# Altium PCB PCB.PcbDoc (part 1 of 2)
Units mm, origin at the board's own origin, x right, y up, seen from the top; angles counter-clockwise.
Board outline 68.58 x 53.34 mm, 4 copper layers (TOP, GND, SIG, BOTTOM), stack 1.586 mm thick; 137 components, 78 nets, 396 pads, 160 vias.
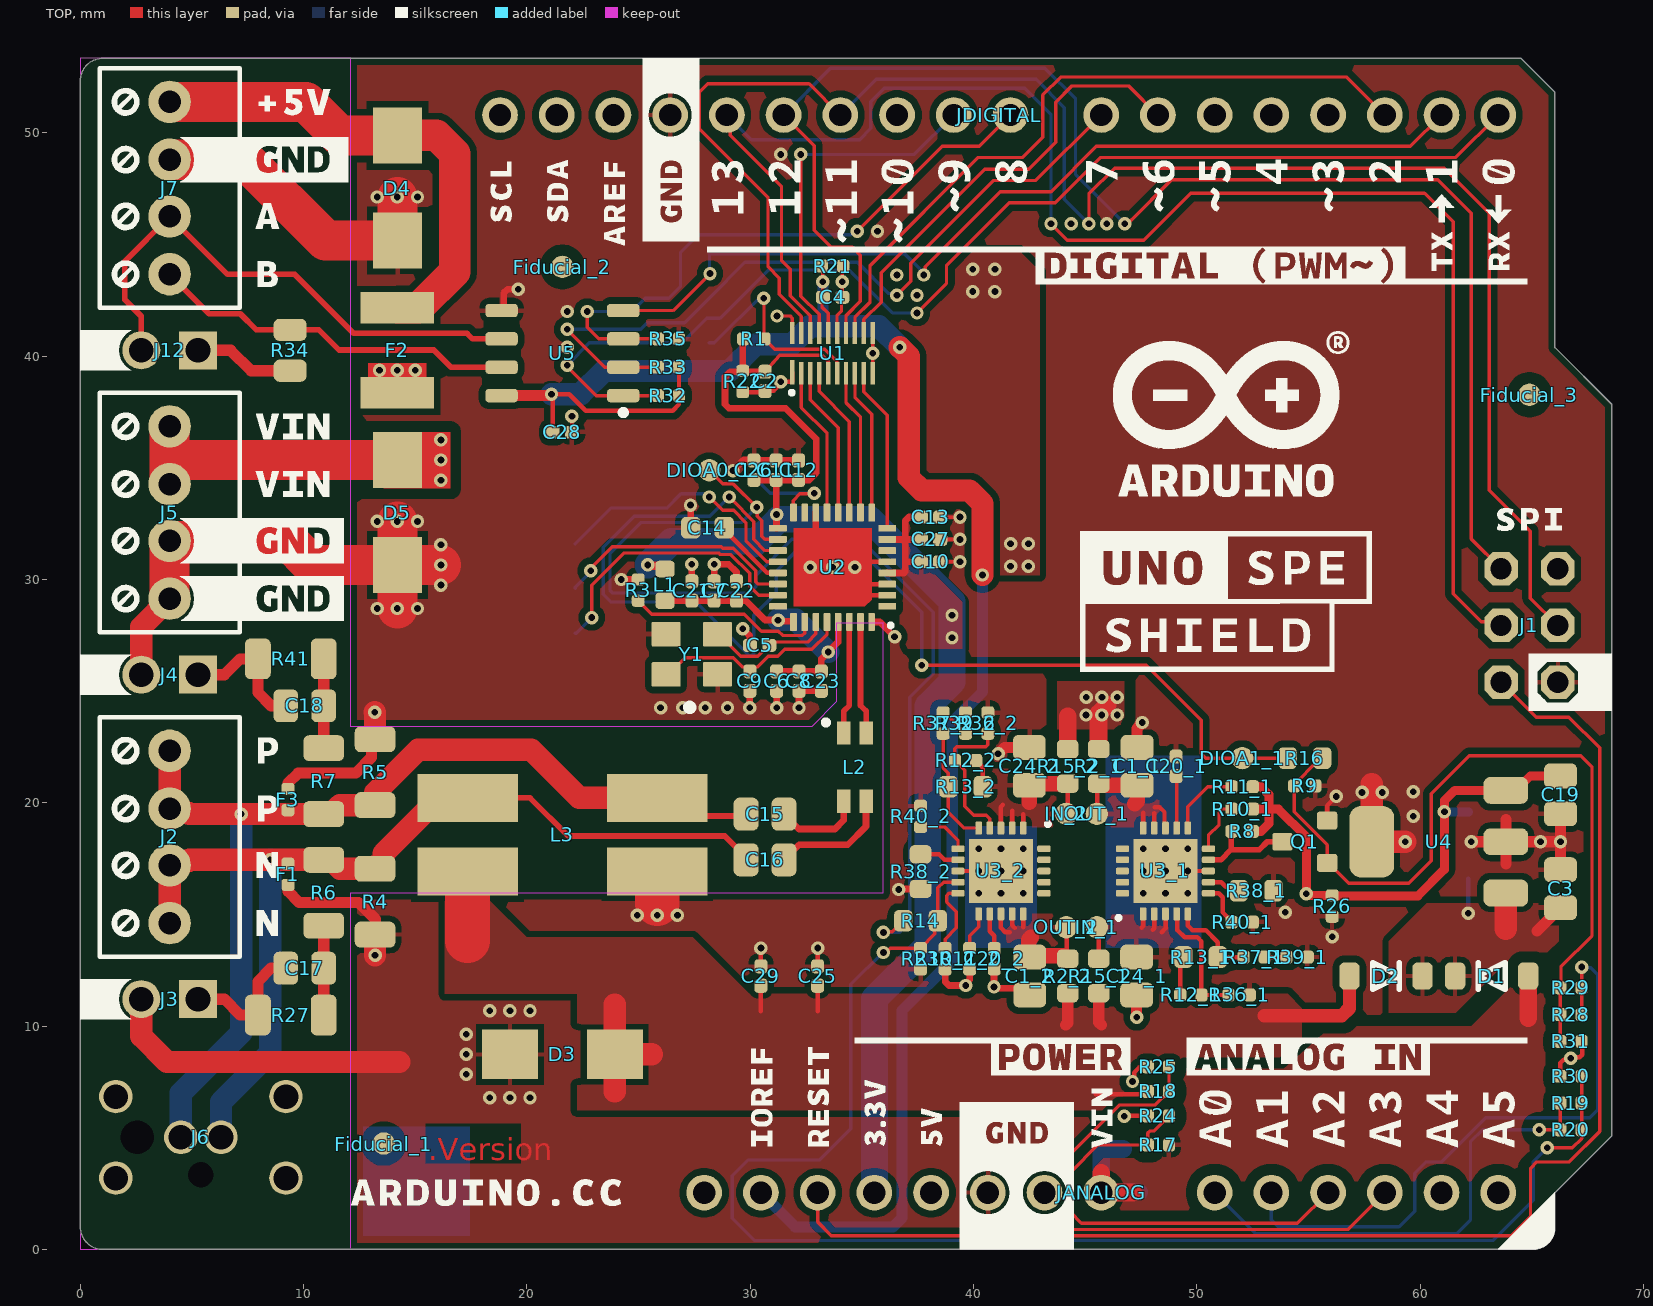
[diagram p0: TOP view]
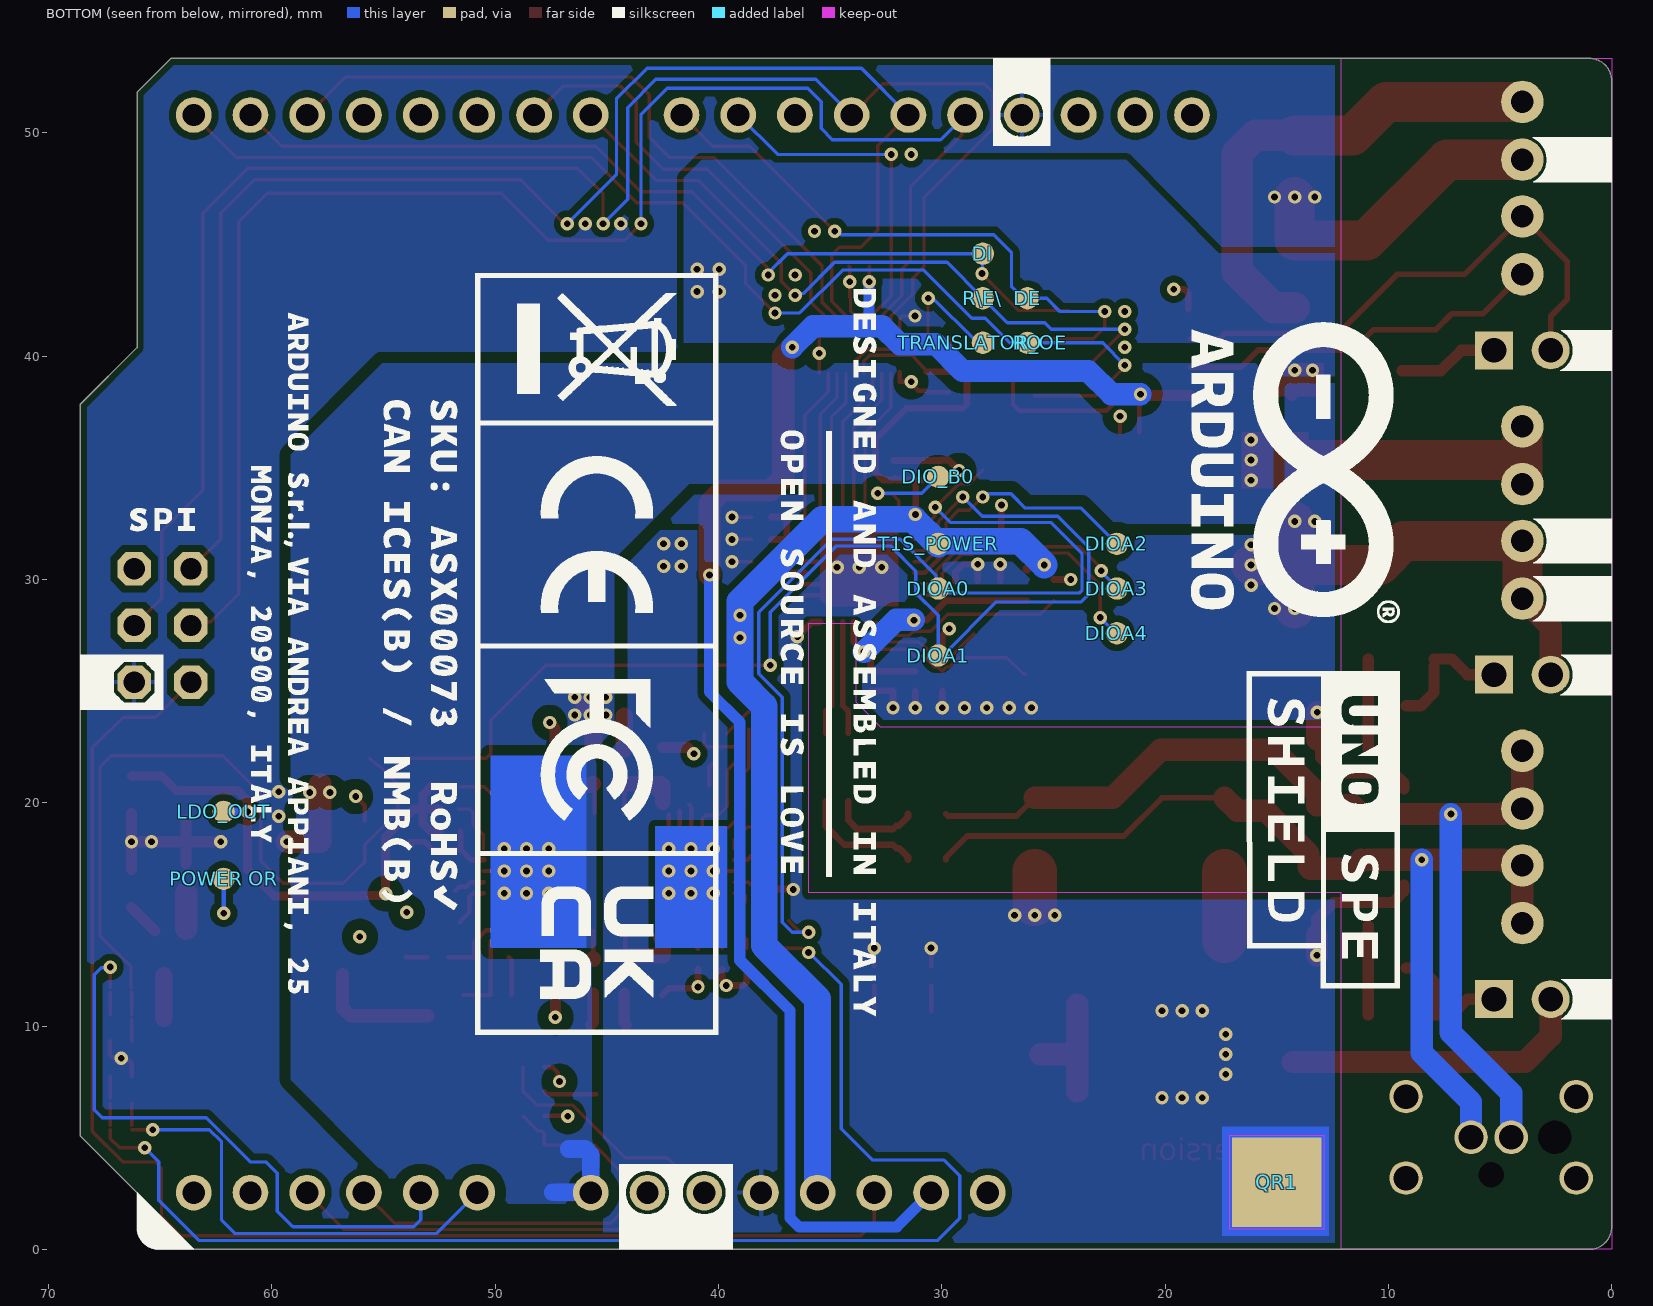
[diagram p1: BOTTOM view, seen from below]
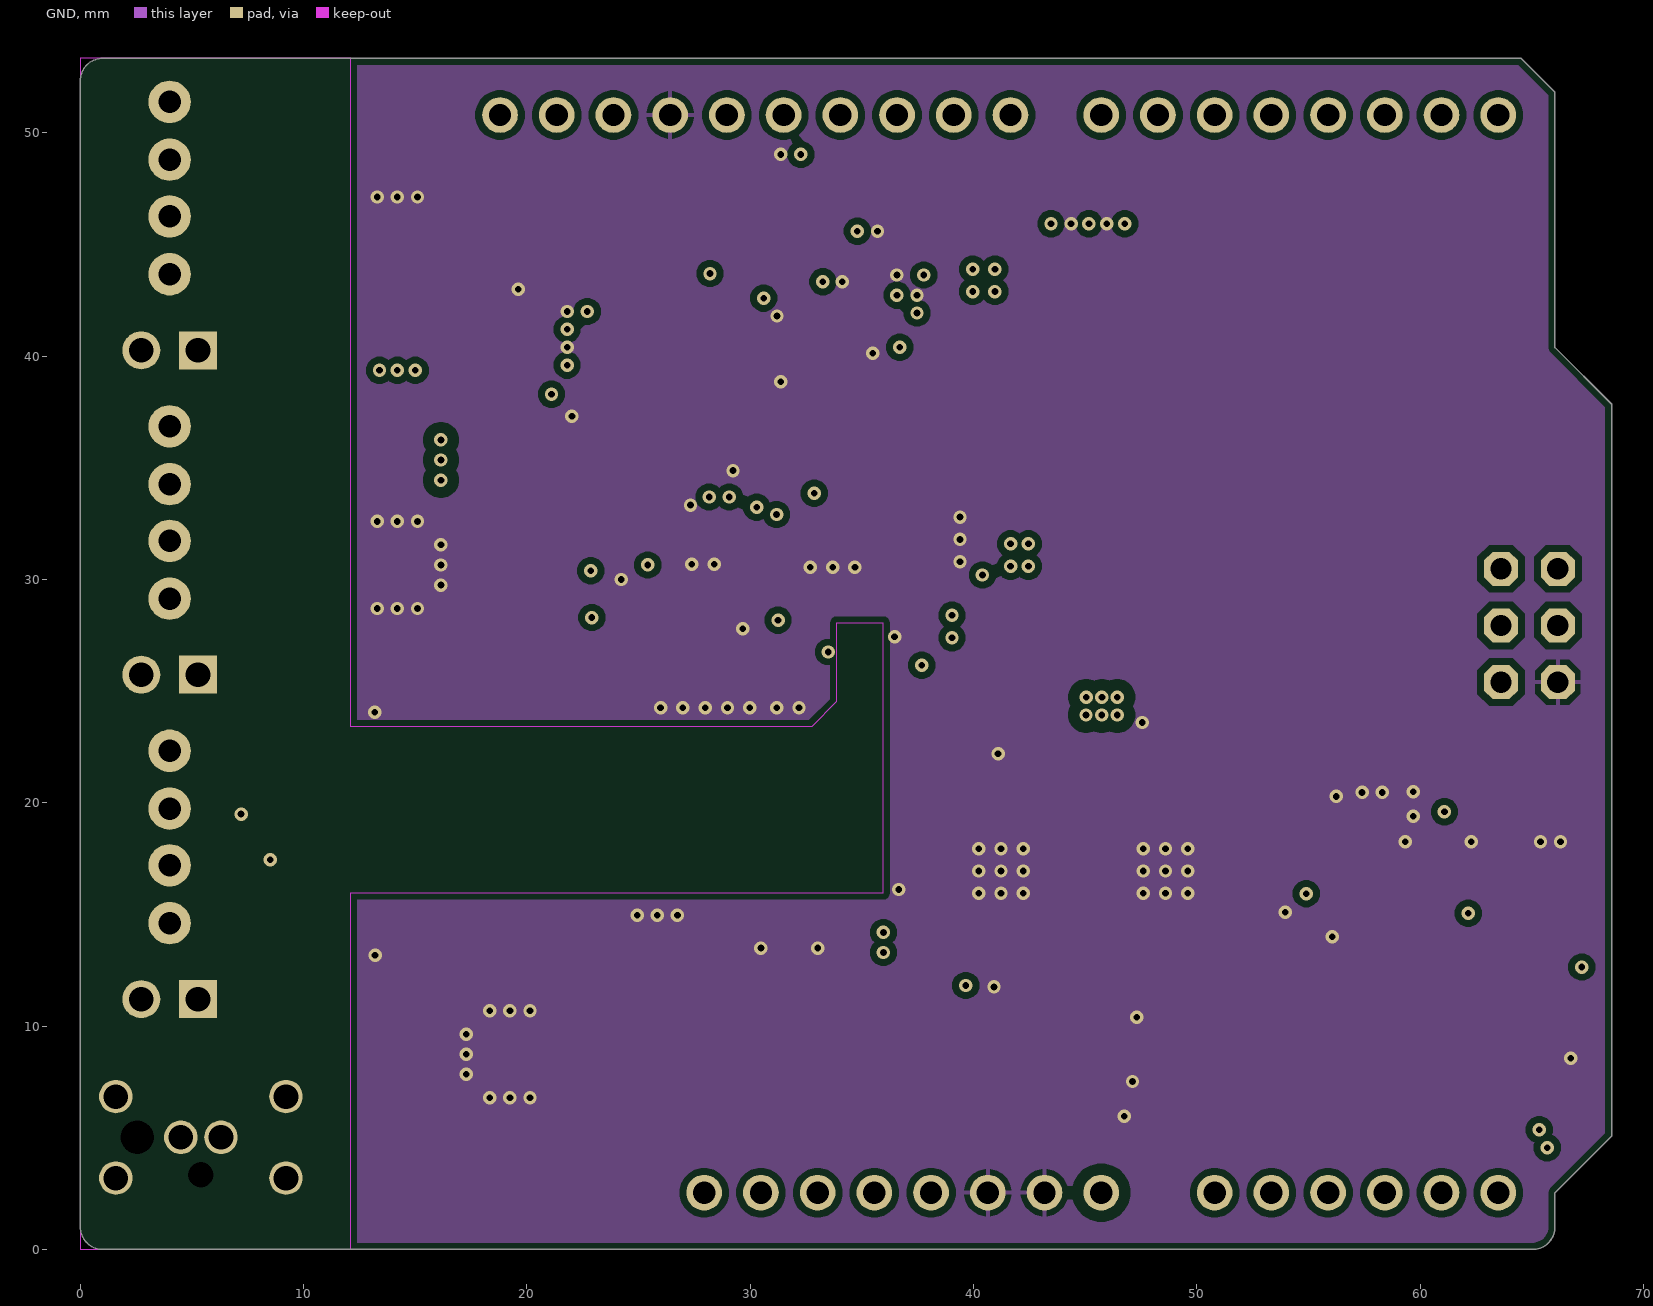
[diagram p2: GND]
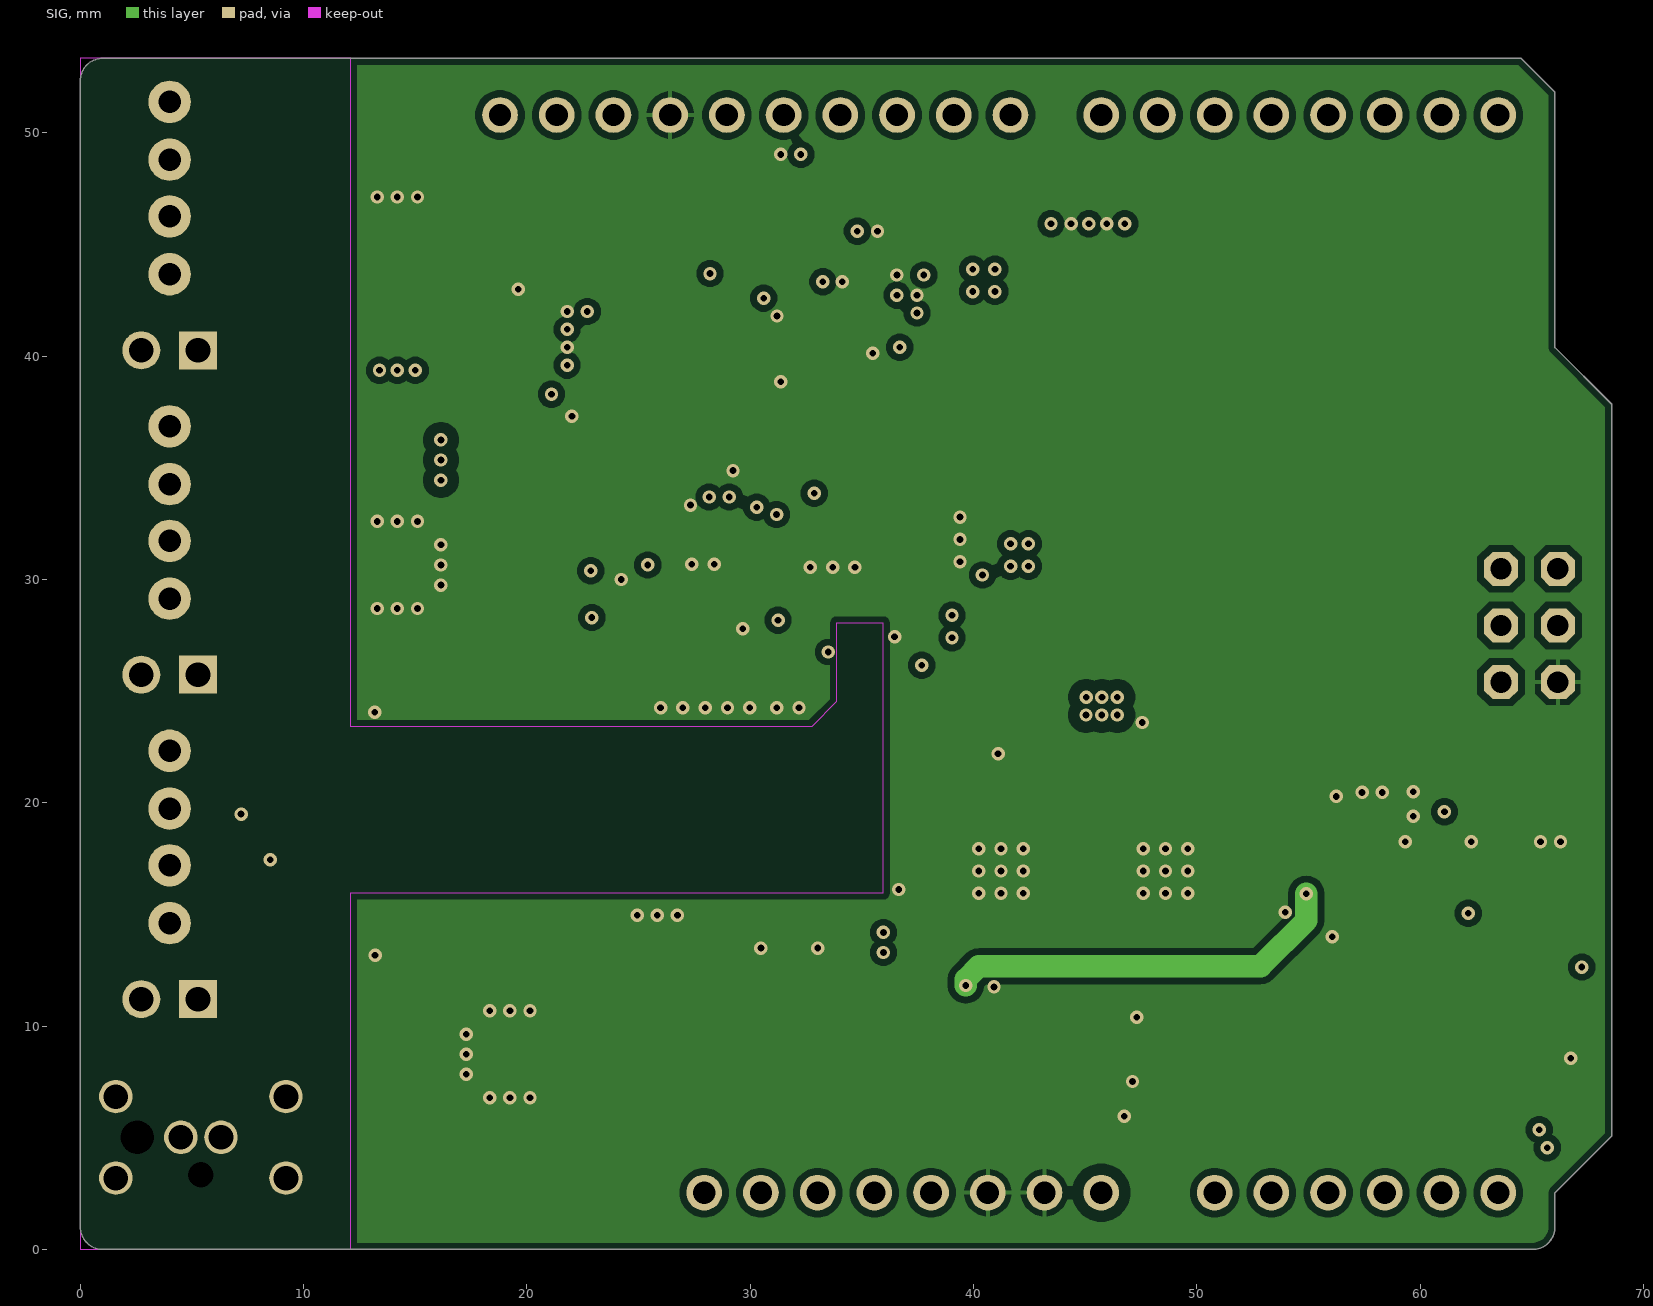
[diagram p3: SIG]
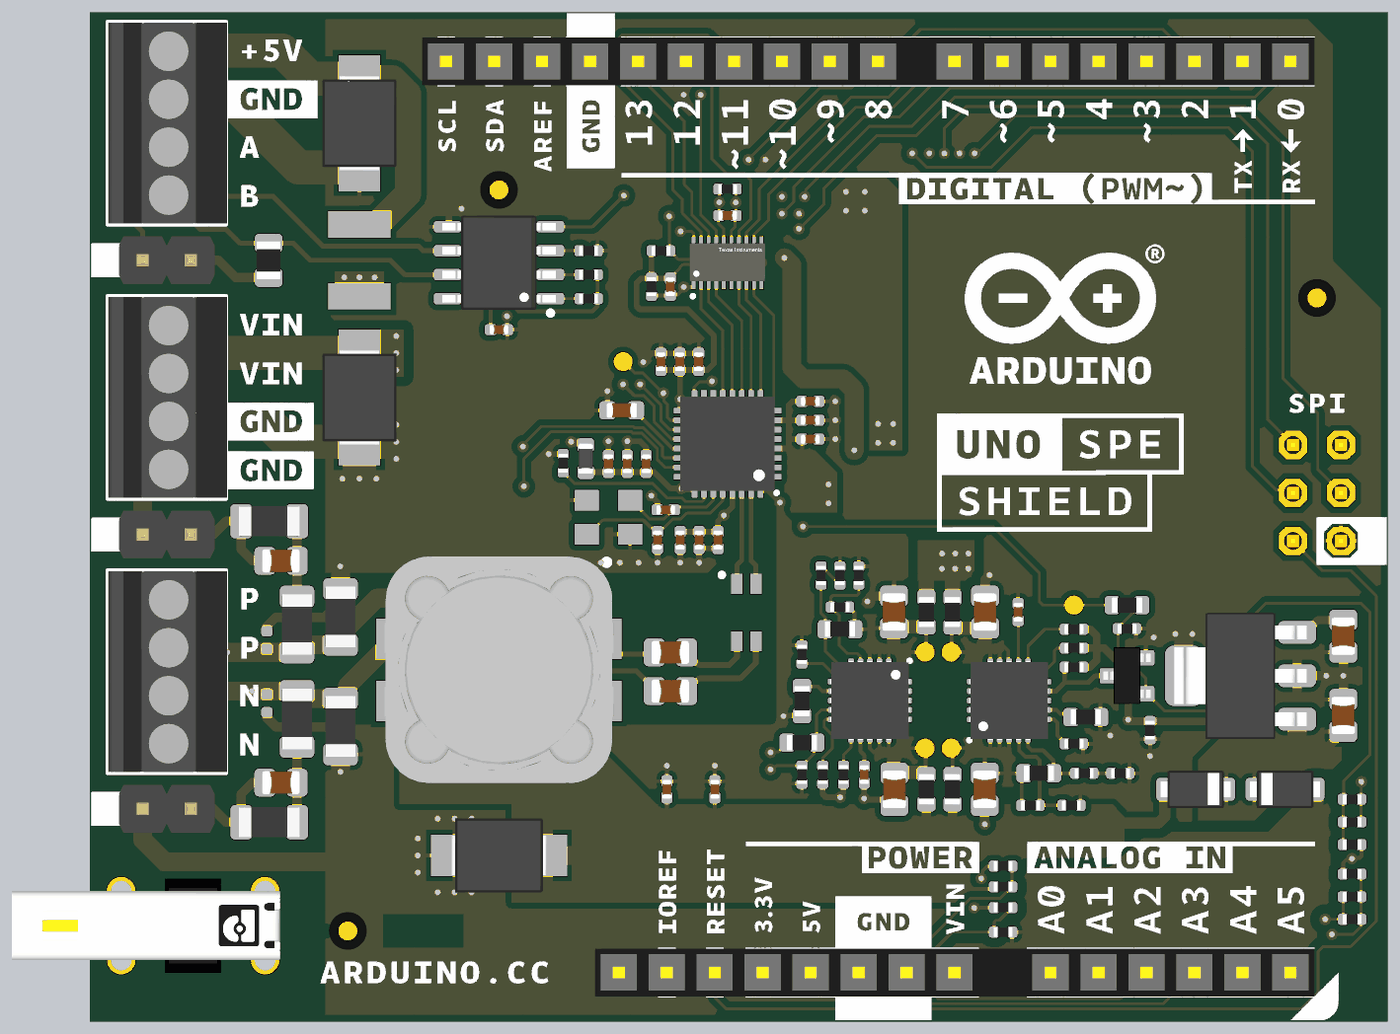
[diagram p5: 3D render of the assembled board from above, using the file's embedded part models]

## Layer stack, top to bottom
Top Solder: solder mask 0.0102, Solder Resist, Dk 3.5
TOP: signal copper 0.018
Dielectric 1: prepreg 0.14, PP-014, Dk 4.2
GND: signal copper 0.035
Dielectric2: core 1.2, FR-4, Dk 4.8
SIG: signal copper 0.035
Dielectric3: prepreg 0.14, PP-014, Dk 4.2
BOTTOM: signal copper 0.018
Bottom Solder: solder mask 0.0102, Solder Resist, Dk 3.5

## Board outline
0,1 0,52.34 cw(c1,52.34) 1,53.34 64.516,53.34 66.04,51.816 66.04,40.386 68.58,37.846 68.58,5.08 66.04,2.54 66.04,1 cw(c65.04,1) 65.04,0 1,0 cw(c1,1)

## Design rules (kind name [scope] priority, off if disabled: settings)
BoardOutlineClearance Silks [(OnLayer('Top Overlay') OR OnLayer('Bottom Overlay'))] p1: gap=0 ignorepadtopadclearanceinfootprint=FALSE
BoardOutlineClearance [All] p2: gap=0.3 ignorepadtopadclearanceinfootprint=FALSE
Clearance VIN_0.5mm [InNet('VIN')] p1: gap=0.5 ignorepadtopadclearanceinfootprint=TRUE
Clearance QR [InComponent('QR1') vs InNet('GND')] p2: gap=0 ignorepadtopadclearanceinfootprint=FALSE
Clearance COPPER_0.3mm [All] p3: gap=0.127 ignorepadtopadclearanceinfootprint=FALSE except(0.3: Arc-Fill Arc-Poly Arc-Region Track-Fill Track-Poly Track-Region SMDPad-Fill SMDPad-Poly SMDPad-Region THPad-Fill THPad-Poly THPad-Region Via-Fill Via-Poly Via-Region Fill-Fill Fill-Poly Fill-Region Poly-Poly Poly-Region Region-Region)
Clearance "Generic clearance 0.127mm" [All] p4: gap=0.127 ignorepadtopadclearanceinfootprint=FALSE
ComponentClearance [All] p1: gap=0.2 collisioncheckmode=3 verticalgap=0 showdistances=TRUE
DiffPairsRouting USB [InDifferentialPairClass('USB')] p1: maxlimit=0.254 minlimit=0.15 mostfreqgap=0.254 toplayer_maxgap=0.15 toplayer_prefgap=0.15 toplayer_minwidth=0.15 toplayer_maxwidth=0.21 toplayer_prefwidth=0.2 midlayer2_mingap=0.24 midlayer2_maxgap=0.24 midlayer2_prefgap=0.24 midlayer2_minwidth=0.15 midlayer2_maxwidth=0.15 midlayer2_prefwidth=0.15 bottomlayer_maxgap=0.15 bottomlayer_prefgap=0.15 bottomlayer_minwidth=0.15 bottomlayer_maxwidth=0.21 bottomlayer_prefwidth=0.2 impedanceprofiledriven=TRUE impedanceprofileid={E6B00C31-4C8E-439C-824F-D2B2CDC26F9C} impedanceprofilevalue=90.000000 maxuncoupledlength=12.7
Height [All] p1: minheight=0 maxheight=30 prefheight=12.7
HoleSize [All] p1: absolutevalues=TRUE maxlimit=30 minlimit=0.3 maxpercent=80.000 minpercent=20.000
HoleToHoleClearance [All] p1: gap=0.25 allowstackedmicrovias=FALSE
MinimumAnnularRing [All] p1: minimumring=0.15
PlaneConnect [All] p1: pad.planeconnectstyle=Relief pad.reliefexpansion=0.508 pad.reliefentries=4 pad.reliefconductorwidth=0.254 pad.reliefairgap=0.254 via.planeconnectstyle=Direct via.reliefexpansion=0.508 via.reliefentries=4 via.reliefconductorwidth=0.254 via.reliefairgap=0.254
PolygonConnect [All] p1: thpad.connectstyle=Relief thpad.reliefconductorwidth=0.2 thpad.reliefentries=4 thpad.polygonreliefangle="90 Angle" thpad.airgapwidth=0.254 smdpad.connectstyle=Relief smdpad.reliefconductorwidth=0.2 smdpad.reliefentries=4 smdpad.polygonreliefangle="90 Angle" smdpad.airgapwidth=0.254 via.connectstyle=Direct via.reliefconductorwidth=0.254 via.reliefentries=4 via.polygonreliefangle="90 Angle" via.airgapwidth=0.254
RoomDefinition U_SWITCH2 [InComponentClass('U_SWITCH2')] p1: confinementstyle=ConfineIn formatcopy=TRUE lockcomponents=FALSE outline 18.045,37.041 18.045,39.371 20.715,39.371 20.715,41.631 22.715,41.631 26.045,41.631 26.045,39.371 28.715,39.371 28.715,37.041 28.44,37.041 28.44,35.646 25.383,35.646 25.383,34.926 21.005,34.926 21.005,34.641 18.755,34.641 18.755,35.646 18.32,35.646 18.32,37.041
RoomDefinition U_SWITCH1 [InComponentClass('U_SWITCH1')] p2: confinementstyle=ConfineIn formatcopy=TRUE lockcomponents=FALSE outline 18.045,30.041 18.045,32.371 20.715,32.371 20.715,34.631 22.715,34.631 26.045,34.631 26.045,32.371 28.715,32.371 28.715,30.041 28.44,30.041 28.44,28.646 25.383,28.646 25.383,27.926 21.005,27.926 21.005,27.641 18.755,27.641 18.755,28.646 18.32,28.646 18.32,30.041
RoomDefinition TOP [InComponentClass('TOP')] p3: confinementstyle=ConfineIn formatcopy=TRUE lockcomponents=FALSE outline 73.6,19.987 86.9,19.987 86.9,30.187 73.6,30.187
RoutingVias StandardVias [All] p1: holewidth=0.3 width=0.6 viastyle="Through Hole" minholewidth=0.3 minwidth=0.6 maxholewidth=0.3 maxwidth=0.6
SMDToCorner [All] p1: distance=39370
SilkToSilkClearance [All] p1: silktosilkclearance=0.2
SilkToSolderMaskClearance [IsPad] p1: minsilkscreentomaskgap=0.15 clearancetoexposedcopper=TRUE
SolderMaskExpansion VIAtented [IsVia] p1: expansion=0.102 istentingtop=TRUE
SolderMaskExpansion [All] p2: expansion=0.05 istentingtop=FALSE
SupplyNets "Schematic Supply Nets_6" [InNet('GND')] p1: voltage=0.000
SupplyNets "Schematic Supply Nets_5" [InNet('LDO_OUT')] p2: voltage=0.000
SupplyNets "Schematic Supply Nets_4" [InNet('IOREF')] p3: voltage=0.000
SupplyNets "Schematic Supply Nets_3" [InNet('VIN')] p4: voltage=0.000
SupplyNets "Schematic Supply Nets_2" [InNet('T1S_POWER')] p5: voltage=0.000
SupplyNets "Schematic Supply Nets_1" [InNet('+3V3')] p6: voltage=0.000
SupplyNets "Schematic Supply Nets" [InNet('+5V')] p7: voltage=0.000
UnConnectedPin [All] p1:
UnRoutedNet [All] p1: checkbadconnections=TRUE
ViasUnderSMD [All] p1: allowed=FALSE
Width StandardTraces [All] p1: maxlimit=5 minlimit=0.127 preferedwidth=0.15
21 further rules are at their usual default settings.

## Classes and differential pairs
component class "U_UART-RS485 Transceiver": C28 DE DI J12 R32 R33 R34 R35 R\E\ RO U5
component class U_T1S_POWER: C3 C19 D1 D2 LDO_OUT "POWER OR" Q1 R8 R9 R23 R26 U4
component class U_SWITCH1: C1_1 C20_1 C24_1 IN_1 OUT_1 R2_1 R10_1 R11_1 R12_1 R13_1 R15_1 R36_1 R37_1 R38_1 R39_1 R40_1 U3_1
channel class SWITCH: U_SWITCH1 U_SWITCH2
component class U_SWITCH2: C1_2 C20_2 C24_2 IN_2 OUT_2 R2_2 R10_2 R11_2 R12_2 R13_2 R15_2 R36_2 R37_2 R38_2 R39_2 R40_2 U3_2
component class U_T1S: C2 C4 C5 C6 C7 C8 C9 C10 C11 C12 C13 C14 C21 C22 C23 C26 C27 L1 R1 R3 R21 R22 T1S_POWER TRANSLATOR_OE U1 U2 Y1
component class TOP: + C15 C16 C17 C18 C25 C29 D3 D4 D5 DIO_B0 DIOA0 DIOA0_1 DIOA1 DIOA1_1 DIOA2 DIOA3 DIOA4 F1 F2 F3 Fiducial_1 Fiducial_2 Fiducial_3 J1 J2 J3 J4 J5 J6 J7 JANALOG JDIGITAL L2 L3 QR1 R4 R5 R6 R7 R14 R16 R17 R18 R19 R20 R24 R25 R27 R28 R29 R30 R31 R41

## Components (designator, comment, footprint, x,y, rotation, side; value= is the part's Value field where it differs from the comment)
C1_1 "GRM21BR61H106ME43L" CAP-0805 47.326,21.632 r90 top value=10µF (schematic designator C1)
C1_2 "GRM21BR61H106ME43L" CAP-0805 42.52,12.242 r270 top value=10µF (schematic designator C1)
C2 "GRM155R61H104KE19D" CAP-0402 30.665,38.87 r90 top value=100nF
C3 "GRM21BR61H106ME43L" CAP-0805 66.29,16.156 r90 top value=10µF
C4 "GRM155R61H104KE19D" CAP-0402 33.69,42.638 r180 top value=100nF
C5 "C0402H100J5GACTU" CAP-0402 30.42,27.05 r0 top value=10pF
C6 "GRM155R60J106ME05D" CAP-0402 31.185,25.45 r90 top value=10µF
C7 "GRM155R61H104KE19D" CAP-0402 28.385,29.485 r270 top value=100nF
C8 "C1005B103K500NT" CAP-0402 32.185,25.45 r90 top value=10nF
C9 "C0402H100J5GACTU" CAP-0402 29.985,25.45 r90 top value=10pF
C10 "GRM155R60J106ME05D" CAP-0402 38.075,30.795 r180 top value=10µF
C11 "C1005B103K500NT" CAP-0402 31.165,34.895 r270 top value=10nF
C12 "GRM155R61H104KE19D" CAP-0402 32.165,34.895 r270 top value=100nF
C13 "GRM155R61H104KE19D" CAP-0402 38.075,32.795 r180 top value=100nF
C14 "GRM188R61C475KAAJD" CAP-0603 28.085,32.32 r0 top value=4.7µF
C15 "08055C104K4T2A" CAP-0805 30.665,19.495 r180 top value=100nF
C16 "08055C104K4T2A" CAP-0805 30.665,17.445 r180 top value=100nF
C17 "CL21B224KBFNNNF" CAP-0805 10.05,12.595 r180 top value=220nF
C18 "CL21B224KBFNNNF" CAP-0805 10.05,24.345 r180 top value=220nF
C19 "GRM21BR61H106ME43L" CAP-0805 66.29,20.356 r270 top value=10µF
C20_1 "GRM155R61H104KE19D" CAP-0402 49.077,21.632 r270 top value=100nF (schematic designator C20)
C20_2 "GRM155R61H104KE19D" CAP-0402 40.929,13.017 r90 top value=100nF (schematic designator C20)
C21 "GRM155R60J106ME05D" CAP-0402 27.385,29.485 r270 top value=10µF
C22 "C1005B103K500NT" CAP-0402 29.385,29.485 r270 top value=10nF
C23 "GRM155R61H104KE19D" CAP-0402 33.185,25.45 r90 top value=100nF
C24_1 "GRM21BR61H106ME43L" CAP-0805 47.305,12.242 r270 top value=10µF (schematic designator C24)
C24_2 "GRM21BR61H106ME43L" CAP-0805 42.499,21.632 r90 top value=10µF (schematic designator C24)
C25 "GRM155R61H104KE19D" CAP-0402 33.02,12.242 r270 top value=100nF
C26 "GRM155R60J106ME05D" CAP-0402 30.165,34.895 r270 top value=10µF
C27 "C1005B103K500NT" CAP-0402 38.075,31.795 r180 top value=10nF
C28 "GRM155R61H104KE19D" CAP-0402 21.59,36.595 r180 top value=100nF
C29 "C1005B103K500NT" CAP-0402 30.48,12.242 r270 top value=10nF
D1 "PMEG6020AELRX" SOD123-1 63.207,12.242 r0 top
D2 "PMEG6020AELRX" SOD123-1 58.473,12.242 r180 top
D3 "SMBJ24CA" SMB_NOPOLARITY 21.59,8.737 r180 top
D4 "SMBJ5.0CA" SMB_NOPOLARITY 14.2,47.53 r90 top
D5 "SMBJ24CA" SMB_NOPOLARITY 14.2,33 r270 top
DE "Test point 1.00mm" TP-1.00MM 26.16,42.595 r180 bottom
DI "Test point 1.00mm" TP-1.00MM 28.16,44.595 r180 bottom
DIO_B0 "Test point 1.00mm" TP-1.00MM 30.16,34.595 r270 bottom
DIOA0 "Test point 1.00mm" TP-1.00MM 30.16,29.595 r270 bottom
DIOA0_1 "Test point 1.00mm" TP-1.00MM 28.165,34.895 r90 top
DIOA1 "Test point 1.00mm" TP-1.00MM 30.16,26.595 r180 bottom
DIOA1_1 "Test point 1.00mm" TP-1.00MM 52.033,22 r90 top
DIOA2 "Test point 1.00mm" TP-1.00MM 22.16,31.595 r270 bottom
DIOA3 "Test point 1.00mm" TP-1.00MM 22.16,29.595 r270 bottom
DIOA4 "Test point 1.00mm" TP-1.00MM 22.16,27.595 r270 bottom
F1 "AVRH10C221KT1R5YA8" "PASSIVE 0402" 9.3,16.795 r90 top
F2 "MF-MSMF050-2-W2" 1812 14.2,40.265 r90 top
F3 "AVRH10C221KT1R5YA8" "PASSIVE 0402" 9.3,20.145 r270 top
Fiducial_1 "Fiducial mark 1mm with 2mm solder" "Fiducial mark 1mm with circle-Footprint-1" 13.59,4.74 r90 top
Fiducial_2 "Fiducial mark 1mm with 2mm solder" "Fiducial mark 1mm with circle-Footprint-1" 21.59,44 r90 top
Fiducial_3 "Fiducial mark 1mm with 2mm solder" "Fiducial mark 1mm with circle-Footprint-1" 64.897,38.273 r90 top
IN_1 "Test point 1.00mm" TP-1.00MM 45.526,14.425 r0 top (schematic designator IN)
IN_2 "Test point 1.00mm" TP-1.00MM 44.156,19.505 r90 top (schematic designator IN)
J1 "RSE2-1-06-SG-3" RSE2-1-06-SG-3 64.897,27.94 r90 top
J2 "DG308-2.54-04P-13-00Z(H)" DG308-2.54-04P 4,18.47 r90 top
J3 "61300211121" 61300211121 4,11.205 r180 top
J4 "61300211121" 61300211121 4,25.735 r180 top
J5 "DG308-2.54-04P-13-00Z(H)" DG308-2.54-04P 4,33 r90 top
J6 "1163797" 1163797 5.4,5.02 r0 top
J7 "DG308-2.54-04P-13-00Z(H)" DG308-2.54-04P 4,47.53 r90 top
J12 "61300211121" 61300211121 4,40.265 r180 top
JANALOG "20TW-988" 20TW-988 45.72,2.54 r0 top locked
JDIGITAL "20TW-987" 20TW-987 45.72,50.8 r180 top locked
L1 "BLM18KG331SN1D" L-0603 26.185,29.76 r270 top
L2 "DLW32MH201XK2L" DLW32MH 34.69,21.6 r270 top
L3 "SRF1260A-221M" SRF1260 21.59,18.57 r180 top
LDO_OUT "Test point 1.00mm" TP-1.00MM 62.16,19.595 r90 bottom
OUT_1 "Test point 1.00mm" TP-1.00MM 45.526,19.505 r0 top (schematic designator OUT)
OUT_2 "Test point 1.00mm" TP-1.00MM 44.156,14.425 r90 top (schematic designator OUT)
"POWER OR" "Test point 1.00mm" TP-1.00MM 62.16,16.595 r90 bottom
Q1 "2N7002KT1G" SOT23 54.84,18.256 r90 top
QR1 "QR CODE 4x4mm" "QR CODE 4x4mm" 15,3 r180 bottom
R1 "CRCW0402100KFKEDC" RES-0402 30.165,40.775 r0 top value=100k
R2_1 "CRCW06030000Z0EAC" RES-0603 45.605,21.632 r270 top value=0 (schematic designator R2)
R2_2 "CRCW06030000Z0EAC" RES-0603 44.22,12.242 r90 top value=0 (schematic designator R2)
R3 "CRCW040212K4FKED" RES-0402 24.985,29.525 r90 top value=12.4k
R4 "RC1206FR-0710KL" RES-1206 13.2,15.57 r270 top value=10k
R5 "RC1206FR-0710KL" RES-1206 13.2,21.37 r90 top value=10k
R6 "RC1206FR-0749R9L" RES-1206 10.9,15.97 r270 top value=49.9
R7 "RC1206FR-0749R9L" RES-1206 10.9,20.97 r90 top value=49.9
R8 "CRCW040210K0FKED" RES-0402 52.033,18.72 r180 top value=10k
R9 "CRCW0402100KFKEDC" RES-0402 54.84,20.756 r0 top value=100k
R10_1 "CRCW040210K0FKED" RES-0402 52.033,19.72 r0 top value=10k (schematic designator R10)
R10_2 "CRCW040210K0FKED" RES-0402 38.729,13.017 r270 top value=10k (schematic designator R10)
R11_1 "CRCW040210K0FKED" RES-0402 52.033,20.72 r0 top value=10k (schematic designator R11)
R11_2 "CRCW040210K0FKED" RES-0402 39.829,13.017 r270 top value=10k (schematic designator R11)
R12_1 "RC0402FR-072M4L" RES-0402 49.733,11.392 r180 top value=2.4M (schematic designator R12)
R12_2 "RC0402FR-072M4L" RES-0402 39.642,21.897 r0 top value=2.4M (schematic designator R12)
R13_1 "RC0603FR-07470KL" RES-0603 50.168,13.092 r180 top value=470k (schematic designator R13)
R13_2 "RC0603FR-07470KL" RES-0603 39.642,20.72 r0 top value=470k (schematic designator R13)
R14 "CRCW06030000Z0EAC" RES-0603 37.629,14.717 r0 top value=0
R15_1 "CRCW06030000Z0EAC" RES-0603 45.605,12.242 r270 top value=0 (schematic designator R15)
R15_2 "CRCW06030000Z0EAC" RES-0603 44.22,21.632 r90 top value=0 (schematic designator R15)
R16 "CRCW06030000Z0EAC" RES-0603 54.842,22 r180 top value=0
R17 "CRCW040210K0FKED" RES-0402 48.28,4.675 r0 top value=10k
R18 "CRCW040210K0FKED" RES-0402 48.28,7.075 r180 top value=10k
R19 "CRCW040210K0FKED" RES-0402 66.757,6.554 r180 top value=10k
R20 "CRCW040210K0FKED" RES-0402 66.757,5.354 r180 top value=10k
R21 "CRCW0402100KFKEDC" RES-0402 33.69,44.038 r0 top value=100k
R22 "CRCW0402100KFKEDC" RES-0402 29.665,38.87 r270 top value=100k
R23 "CRCW04021K50JNED" RES-0402 37.629,13.017 r270 top value=1.5k
R24 "CRCW04021K50JNED" RES-0402 48.28,5.975 r0 top value=1.5k
R25 "CRCW04021K50JNED" RES-0402 48.28,8.175 r0 top value=1.5k
R26 "CRCW0402100KFKEDC" RES-0402 56.064,15.374 r270 top value=100k
R27 "RV1206FR-07100KL" RES-1206 9.425,10.495 r180 top value=100k
R28 "CRCW040210K0FKED" RES-0402 66.757,10.513 r0 top value=10k
R29 "CRCW040210K0FKED" RES-0402 66.757,11.713 r0 top value=10k
R30 "CRCW040210K0FKED" RES-0402 66.757,7.754 r0 top value=10k
R31 "CRCW040210K0FKED" RES-0402 66.757,9.313 r180 top value=10k
R32 "CRCW040210K0FKED" RES-0402 26.336,38.235 r0 top value=10k
R33 "CRCW040210K0FKED" RES-0402 26.336,39.505 r0 top value=10k
R34 "RMCF0805FT120R" RES-0805 9.395,40.265 r90 top value=120
R35 "CRCW040210K0FKED" RES-0402 26.336,40.775 r180 top value=10k
R36_1 "CRCW0402910KFKED" RES-0402 51.894,11.392 r180 top value=910k (schematic designator R36)
R36_2 "CRCW0402910KFKED" RES-0402 40.642,23.572 r270 top value=910k (schematic designator R36)
R37_1 "CRCW040212K4FKED" RES-0402 52.568,13.092 r180 top value=12.4k (schematic designator R37)
R37_2 "CRCW040212K4FKED" RES-0402 38.642,23.572 r270 top value=12.4k (schematic designator R37)
R38_1 "CRCW06032K20FKEAC" RES-0603 52.659,16.066 r180 top value=2.2k (schematic designator R38)
R38_2 "CRCW06032K20FKEAC" RES-0603 37.629,16.917 r90 top value=2.2k (schematic designator R38)
R39_1 "CRCW040212K4FKED" RES-0402 54.491,13.092 r180 top value=12.4k (schematic designator R39)
R39_2 "CRCW040212K4FKED" RES-0402 39.642,23.572 r270 top value=12.4k (schematic designator R39)
R40_1 "RC0402JR-10150KL" RES-0402 52.032,14.653 r180 top value=150k (schematic designator R40)
R40_2 "RC0402JR-10150KL" RES-0402 37.629,19.39 r270 top value=150k (schematic designator R40)
R41 "RV1206FR-07100KL" RES-1206 9.425,26.445 r180 top value=100k
R\E\ "Test point 1.00mm" TP-1.00MM 28.16,42.595 r90 bottom
RO "Test point 1.00mm" TP-1.00MM 26.16,40.595 r180 bottom
T1S_POWER "Test point 1.00mm" TP-1.00MM 30.16,31.595 r180 bottom
TRANSLATOR_OE "Test point 1.00mm" TP-1.00MM 28.16,40.605 r270 bottom
U1 "TXB0108DQSR" FP-DQS0020A-MFG 33.69,40.138 r90 top
U2 "LAN8651B1-E/LMX" PQFN50P500X500X100_HS-33N 33.69,30.545 r180 top
U3_1 "MAX17613AATP+T" QFN50P400X400X80_HS-21N 48.596,16.945 r90 top (schematic designator U3)
U3_2 "MAX17613AATP+T" QFN50P400X400X80_HS-21N 41.229,16.945 r270 top (schematic designator U3)
U4 "MCP1799T-5002H/DB" SOT223-3 60.84,18.256 r180 top
U5 "XR33058IDTR-F" SOIC8 21.59,40.14 r180 top
Y1 "12.88667" CRYSTAL3.2X2.5 27.385,26.65 r0 top

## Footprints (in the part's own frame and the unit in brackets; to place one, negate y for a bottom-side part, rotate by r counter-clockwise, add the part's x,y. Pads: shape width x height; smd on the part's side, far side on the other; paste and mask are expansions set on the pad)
20TW-987 [mm] "Jdigital for UNO shields 18 pin with labels"
  round 1.6 hole 1: 1(-17.78,0) 2(-15.24,0) 3(-12.7,0) 4(-10.16,0) 5(-7.62,0) 6(-5.08,0) 7(-2.54,0) 8(0,0) 9(4.064,0) 10(6.604,0) 11(9.144,0) 12(11.684,0) 13(14.224,0) 14(16.764,0) 15(19.304,0) 16(21.844,0) 17(24.384,0) 18(26.924,0)
  body extent -19.05,-1.32 28.2,1.32, height 8.6
20TW-988 [mm] "Janalog for UNO shields 14 pin with labels on side"
  round 1.6 hole 1: 1(-17.78,0) 2(-15.24,0) 3(-12.7,0) 4(-10.16,0) 5(-7.62,0) 6(-5.08,0) 7(-2.54,0) 8(0,0) 9(5.08,0) 10(7.62,0) 11(10.16,0) 12(12.7,0) 13(15.24,0) 14(17.78,0)
  body extent -19.05,-1.32 19.05,1.32, height 8.6
1812 [mm] "Chip Capacitor, Body 4.5x3.2mm, IPC High Density"
  rect 1.4x3.3 smd: 1(-1.9,0) 2(1.9,0)
  body extent -2.4,-1.7 2.4,1.7, height 1.4
1163797 [mm]
  round 1.5 hole 1.1: 1(-0.9,0) 2(0.9,0) SHIELD(-3.81,-1.825) SHIELD(-3.81,1.825) SHIELD(3.81,-1.825) SHIELD(3.81,1.825)
  round 0.5 hole 1.5 unplated: FIX(-2.85,0)
  round 0.5 hole 1.15 unplated: FIX(0,-1.675)
  body extent -9.6,-2.5 4.6,2.5, height 5.99
61300211121 [mm] "Pin Header, pitch 2.54 mm, THT, Vertical, single row, 2p"
  rect 1.7x1.7 hole 1.1: 1(-1.27,0)
  round 1.7 hole 1.1: 2(1.27,0)
  body extent -2.54,-1.27 2.54,1.27, height 8.57
CAP-0402 [mm] "Chip Capacitor, 2-Leads, Body  0402 (in) 1005 (mm), IPC Medium Density"
  rrect52% 0.63x0.58 smd mask+0.05: 1(-0.435,0) 2(0.435,0)
  body extent -0.5,-0.25 0.5,0.25, height 0.5
CAP-0603 [mm] "Chip Capacitor, Body 0603 imperial,1.6x0.8mm, IPC High Density"
  rrect51% 0.87x0.97 smd mask+0.05: 1(-0.75,0) 2(0.75,0)
  body extent -0.8,-0.4 0.8,0.4, height 0.8
CAP-0805 [mm] "Chip Capacitor, Body 0805 imperial, 2.0x1.2mm, IPC Medium Density"
  rrect45% 1.11x1.47 smd mask+0.05: 1(-0.85,0) 2(0.85,0)
  body extent -1,-0.62 1,0.63, height 1.25
CRYSTAL3.2X2.5 [mm]
  rrect10% 1.3x1.1 smd: 1(-1.15,-0.9) 2(1.15,-0.9) 3(1.15,0.9) 4(-1.15,0.9)
  body extent -1.65,-1.14 1.52,1.27, height 0.6
DG308-2.54-04P [mm]
  round 1.9 hole 1 mask+0.05: 1(-3.86,0) 2(-1.27,0) 3(1.27,0) 4(3.86,0)
  silkscreen extent -5.37,-3.14 5.37,3.14, body extent -5.32,-3.2 5.32,3.1, height 8.63
DLW32MH [mm]
  rect 1.05x0.6 smd mask+0.05: 1(-1.525,-0.5) 2(1.525,-0.5) 3(1.525,0.5) 4(-1.525,0.5)
  silkscreen extent -2.05,-1.35 -1.95,-1.25, body extent -1.6,-1.25 1.6,1.25, height 2.5
"Fiducial mark 1mm with circle-Footprint-1" [mm]
  round 1 smd paste-10 mask+0.5: 1(0,0)
  TOP pour cut-out: 0,1 0.383,0.924 0.707,0.707 0.924,0.383 1,0 1,0 0.924,-0.383 0.707,-0.707 0.383,-0.924 0,-1 0,-1 -0.383,-0.924 -0.707,-0.707 -0.924,-0.383 -1,0 -1,0 -0.924,0.383 -0.707,0.707 -0.383,0.924 0,1
FP-DQS0020A-MFG [mm]
  rect 1.1x0.2 smd paste-1000 mask+0.05: 1(-0.85,1.8)
  rect 1x0.2 smd paste-1000 mask+0.05: 2(-0.9,1.4) 3(-0.9,1) 4(-0.9,0.6) 5(-0.9,0.2) 6(-0.9,-0.2) 7(-0.9,-0.6) 8(-0.9,-1) 9(-0.9,-1.4) 10(-0.9,-1.8) 11(0.9,-1.8) 12(0.9,-1.4) 13(0.9,-1) 14(0.9,-0.6) 15(0.9,-0.2) 16(0.9,0.2) 17(0.9,0.6) 18(0.9,1) 19(0.9,1.4) 20(0.9,1.8)
  silkscreen extent -1.82,1.78 -1.72,1.88, body extent -0.98,-2 1.02,2, height 0.55
L-0603 [mm] "Chip Inductor - Body 0603 imperial,1.6x0.8mm, IPC High Density"
  rrect51% 0.75x0.87 smd mask+0.05: 1(-0.71,0) 2(0.71,0)
  body extent -0.8,-0.4 0.8,0.4, height 0.8
"PASSIVE 0402" [mm]
  rrect51% 0.55x0.58 smd mask+0.05: 1(-0.475,0) 2(0.475,0)
  body extent -0.5,-0.25 0.5,0.25, height 0.35
PQFN50P500X500X100_HS-33N [mm] "PQFN, 32-Leads, Body 5,00x5,00mm, Pitch 0,50mm, Thermal Pad 3,40x3,40mm, IPC Medium Density"
  rrect25% 0.8x0.3 smd paste+0 mask+0.05: 1(-2.45,1.75) 2(-2.45,1.25) 3(-2.45,0.75) 4(-2.45,0.25) 5(-2.45,-0.25) 6(-2.45,-0.75) 7(-2.45,-1.25) 8(-2.45,-1.75) 17(2.45,-1.75) 18(2.45,-1.25) 19(2.45,-0.75) 20(2.45,-0.25) 21(2.45,0.25) 22(2.45,0.75) 23(2.45,1.25) 24(2.45,1.75)
  rrect25% 0.3x0.8 smd paste+0 mask+0.05: 9(-1.75,-2.45) 10(-1.25,-2.45) 11(-0.75,-2.45) 12(-0.25,-2.45) 13(0.25,-2.45) 14(0.75,-2.45) 15(1.25,-2.45) 16(1.75,-2.45) 25(1.75,2.45) 26(1.25,2.45) 27(0.75,2.45) 28(0.25,2.45) 29(-0.25,2.45) 30(-0.75,2.45) 31(-1.25,2.45) 32(-1.75,2.45)
  round 0.025 smd paste-10: 33(0,0)
  TOP region: -1.45,1.75 -1.75,1.45 -1.75,-1.75 1.75,-1.75 1.75,1.75
  silkscreen extent -2.65,2.55 -2.55,2.65, body extent -2.5,-2.5 2.5,2.5, height 1
QFN50P400X400X80_HS-21N [mm] "QFN, 20-Leads, Body 4,00x4,00mm, Pitch 0,50mm, Thermal Pad 2,85x2,85mm, IPC Medium Density"
  rrect50% 0.6x0.3 smd mask+0.05: 1(-1.925,1) 2(-1.925,0.5) 3(-1.925,0) 4(-1.925,-0.5) 5(-1.925,-1) 11(1.925,-1) 12(1.925,-0.5) 13(1.925,0) 14(1.925,0.5) 15(1.925,1)
  rrect50% 0.3x0.6 smd mask+0.05: 6(-1,-1.925) 7(-0.5,-1.925) 8(0,-1.925) 9(0.5,-1.925) 10(1,-1.925) 16(1,1.925) 17(0.5,1.925) 18(0,1.925) 19(-0.5,1.925) 20(-1,1.925)
  rect 2.85x2.85 smd paste-50 mask+0.05: 21(0,0)
  silkscreen extent -2.15,2.05 -2.05,2.15, body extent -2.1,-2.1 2.1,2.1, height 0.8
"QR CODE 4x4mm" [mm]
  rect 4x4 smd paste-2539.97 mask+0.1: PAD(0,0)
  TOP keep-out region: -2.1,2.1 2.1,2.1 2.1,-2.1 -2.1,-2.1
RES-0402 [mm] "Chip Resistor, 2-Leads, Body  0402 (in) 1005 (mm), IPC Medium Density"
  rrect51% 0.55x0.58 smd mask+0.05: 1(-0.475,0) 2(0.475,0)
  body extent -0.5,-0.25 0.5,0.25, height 0.34
RES-0603 [mm] "Chip Resistor - Body 0603 imperial,1.6x0.8mm, IPC High Density"
  rrect51% 0.82x0.97 smd mask+0.05: 1(-0.775,0) 2(0.775,0)
  body extent -0.8,-0.4 0.8,0.4, height 0.43
RES-0805 [mm] "Chip Resistor - Body 0805 imperial, 2.0x1.2mm, IPC Medium Density"
  rrect51% 0.99x1.47 smd mask+0.05: 1(-0.915,0) 2(0.915,0)
  body extent -1,-0.62 1,0.63, height 0.58
RES-1206 [mm] "Chip Resistor, 2-Leads, 1206 (in) 3216 (mm), IPC Medium Density"
  rrect43% 1.16x1.82 smd mask+0.05: 1(-1.475,0) 2(1.475,0)
  body extent -1.6,-0.8 1.6,0.8, height 0.7
RSE2-1-06-SG-3 [mm]
  oct 1.501x1.501 / inner oct 1.524x1.524 / far side oct 1.501x1.501 hole 0.95: 1(2.54,1.27) 2(2.54,-1.27) 3(0,1.27) 4(0,-1.27) 5(-2.54,1.27) 6(-2.54,-1.27)
  body extent -4,-2.5 4,2.5, height 10.8
SMB_NOPOLARITY [mm]
  rect 2.5x2.2 smd: 1(-2.35,0) 2(2.35,0)
  body extent -2.55,-1.97 2.55,1.97, height 2.62
SOD123-1 [mm]
  rrect50% 0.91x1.22 smd: A(1.635,0) C(-1.635,0)
  silkscreen extent -0.6,-0.6 0.6,0.6, body extent -1.85,-1 1.85,1, height 1.2
SOIC8 [mm] "SOIC, 8-Leads, Body 4.90x3.90mm, Pitch 1.27mm, Thermal Pad 3.00x2.50mm, IPC Medium Density"
  rrect50% 1.45x0.6 smd: 1(-2.725,1.905) 2(-2.725,0.635) 3(-2.725,-0.635) 4(-2.725,-1.905) 5(2.725,-1.905) 6(2.725,-0.635) 7(2.725,0.635) 8(2.725,1.905)
  silkscreen extent -2.85,2.54 -2.6,2.79, body extent -3,-2.5 3,2.5, height 1.75
SOT23 [mm]
  rrect25% 0.8x0.9 smd: 1(-0.95,-1) 2(0.95,-1) 3(0,1)
  body extent -1.5,-1.25 1.5,1.25, height 1.05
SOT223-3 [mm]
  rrect50% 2x1.2 smd: 1(-3,2.3) 2(-3,0) 3(-3,-2.3)
  rrect50% 2x3.2 smd: 4(3,0)
  body extent -3.5,-3.35 3.5,3.35, height 1.8
SRF1260 [mm]
  rect 4.5x2.15 smd: 1(-4.25,-1.65) 2(-4.25,1.65) 3(4.25,1.65) 4(4.25,-1.65)
  silkscreen extent -5.75,-5.75 -5.65,-5.65, body extent -6.06,-6 6.06,6, height 6.11
TP-1.00MM [mm]
  rrect100% 1x1 smd paste-2.54: X(0,0)

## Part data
C1_1 C1_2 C3 C19 C24_1 C24_2: library part C0158-A.3, "CAP CHIP 0805 10uF 20% 50V X5R", Case Code (Imperial)=0805, Dielectric=X5R, Manufacturer="Murata Electronics", Tolerance=20%, Voltage=50V
C2 C4 C7 C12 C13 C20_1 C20_2 C23 C25 C28: library part C0015-A.14, "CAP CHIP 0402 100nF 10% 50V X5R", Case Code (Imperial)=0402, Dielectric=X5R, Manufacturer=Murata, Tolerance=10%, Voltage=50V
C5 C9: library part C0006-A.14, "CAP CHIP 0402 10pF 5% 50V C0G", Case Code (Imperial)=0402, Dielectric=C0G, Manufacturer=KEMET, Tolerance=5%, Voltage=50V
C6 C10 C21 C26: library part C0091-A.13, "CAP CHIP 0402 10uF 20% X5R 6.3V", Case Code (Imperial)=0402, Dielectric=X5R, Manufacturer=Murata, Tolerance=20%, Voltage=6.3V
C8 C11 C22 C27 C29: library part C0009-A.15, "CAP CHIP 0402 10nF 10% 50V X7R", Case Code (Imperial)=0402, Dielectric=X7R, Manufacturer=Hottech, Manufacturer 2="Murata Electronics", Manufacturer 3=YAGEO, Part number 2=CC0402KRX7R9BB103, Tolerance=10%, Voltage=50V
C14: library part C0054-A.16, "CAP CHIP 0603 4.7uF 10% 16V X5R", Case Code (Imperial)=0603, Dielectric=X5R, Manufacturer=Murata, Manufacturer 3="Samsung Electro-Mechanics", Part number 2=GRM188R61C475KE11D, Part number 3=CL10A475KO8NNNC, Tolerance=10%, Voltage=16V
C15 C16: library part C0148-A.1, "CAP CHIP 0805 100nF 10% 50V X7R", Case Code (Imperial)=0805, Dielectric=X7R, Manufacturer="KYOCERA AVX", Tolerance=10%, Voltage=50V
C17 C18: library part C0048-A.5, "CAP CHIP 0805 220nF 10% 50V X5R", Case Code (Imperial)=0805, Dielectric=X5R, Manufacturer="Samsung Electro-Mechanics", Tolerance=10%, Voltage=50V
D1 D2: library part D0026-A.6, "DIODE SCHOTTKY SMD 2A 60V SOD123FL", Forward Current=2A, Forward Voltage=0.6V, Manucturer Part Number 2=SS26L, Manufacturer=Nexperia
D3 D5: library part D0070-A.2, "TVS BIDIRECTIONAL SMD Vr 24V, Vbr min 26.7V, 600W, SMB", Manufacturer=Littlefuse, Manufacturer 2=Bourns, Manufacturer 3=Hottech
D4: library part D0077-A.1, "TVS BIDIRECTIONAL SMD Vr 5V, Vbr min 6.4V, 600W, SMB", Manufacturer=Littelfuse
DE DI DIO_B0 DIOA0 DIOA0_1 DIOA1 DIOA1_1 DIOA2 DIOA3 DIOA4 IN_1 IN_2 LDO_OUT OUT_1 OUT_2 "POWER OR" R\E\ RO T1S_POWER TRANSLATOR_OE: library part UT0013-A.6, Manufacturer="This is not a component"
F1 F3: library part P0023-1, "VARISTOR 0402, VDC 70V, 1.5pF", Capacity=1.5pF, Circuit DC Voltage-Max=70V, Manufacturer=TDK
F2: library part P0002-A.7, "PTC RESET FUSE 15V 500MA 1812 LOGO OO ARDUINO", Case Code (Imperial)=1812, Case Code (Metric)=4532, Current Rating=100A, Hold Current=500mA, Manufacturer=Bourns, Max Operating Temperature=85°C, Min Operating Temperature=-40°C, Operating Supply Voltage=15V, Package Quantity=2000, Power Dissipation=800mW, Resistance=150mR, Trip Current=1A
Fiducial_1 Fiducial_2 Fiducial_3: library part UT0024-A.6
J1: library part J0481-A.2, "CONN header 2.54mm, 2x3 positions, female heigth 8.5mm male heigth 11.4mm", Manufacturer="Adam Tech"
J2 J5 J7: library part J0438-A.5, "CONN SCREW TERMINAL 4 POS pitch 2.54mm height 8.6mm BLACK", Manufacturer=Degson
J3 J4 J12: library part J0182-A.4, "CONN HEADER MALE VERT 2POS 2.54MM", Manufacturer="Wurth Electronics", Manufacturer 2=4UCON, Manufacturer Part Number 2=21TW-507
J6: library part J0425-A.5, "CONN 10BASE-T1S, CatB, Single Pair Ethernet", Manufacturer=Phoenix, Manufacturer 2=Weidmuller, Part number 2=2726010000
JANALOG: library part J0407-A.8, "JANALOG UNO SHIELDS header 2.54mm with 8+6 pins, custom 5.08mm pitch between them, custom silkscreen print on side, custom 14.95mm pins length", Manufacturer=4UCONN
JDIGITAL: library part J0408-A.7, "JDIGITAL UNO SHIELDS header 2.54mm with 8+10 pins, custom 4.06mm pitch between them, custom silkscreen print on side, custom 14.95mm pins length", Manufacturer=4UCONN
L1: library part I0002-A.7, "FERRITE SMD 0603 330 OHM 1LN", Case Code (Imperial)=0603, Case Code (Metric)=1608, DC Resistance (DCR)=80mR, Manufacturer=Murata, Max DC Current=1.7A, Max Operating Temperature=125°C, Min Operating Temperature=-55°C, Package Quantity=1, Test Frequency=100MHz, Tolerance=25%
L2: library part I0108-A.2, "CHOKE SMD 200uH at 0.1MHz, 70mA DC 4R 3.2x2.2x2.5mm", Inductance=200µH, Manufacturer=Murata
L3: library part I0110-A.2, "COUPLED INDUCTORS SMD Parallel 220uH, IRMS 1.19A, ISAT 1.51A, DCR 1R41 12.5x12.5x6mm", Inductance=220µH, Manufacturer=Bourns, Manufacturer 2=K-WELL, Part number 2=1205PMB-221M, Tolerance=20%
Q1: library part T0004-A.10, "MOSFET N-CH 60V 300mA ESD prot. SOT23", Manufacturer="On Semiconductor", Manufacturer 2=Hottech, Manufacturer Part Number 2=2N7002K
QR1: library part QR-0001-A.3, "QR CODE 4x4mm on layer 34 (This is not a component)", Manufacturer="This is not a component"
R1 R9 R21 R22 R26: library part R0001-A.24, "RES CHIP 0402 100k 1% 1/16W", Case Code (Imperial)=0402, Manufacturer=Vishay, Power=62.5mW, Temperature Coefficient=100ppm, Tolerance=1%
R2_1 R2_2 R14 R15_1 R15_2 R16: library part R0096-A.22, "RES CHIP 0603 0R 1/10W", Case Code (Imperial)=0603, Manufacturer=Vishay, Power=100mW, Temperature Coefficient=0ppm, Tolerance=0%
R3 R37_1 R37_2 R39_1 R39_2: library part R0027-A.24, "RES CHIP 0402 12k4 1% 1/16W", Case Code (Imperial)=0402, Manufacturer=Vishay, Power=62.5mW, Temperature Coefficient=100ppm, Tolerance=1%
R4 R5: library part R0298-A.1, "RES CHIP 1206 10k 1% 1/4W", Case Code (Imperial)=1206, Manufacturer=YAGEO, Power=250mW, Temperature Coefficient=100ppm, Tolerance=1%
R6 R7: library part R0301-A.1, "RES CHIP 1206 49R9 1% 1/4W", Case Code (Imperial)=1206, Manufacturer=YAGEO, Power=250mW, Temperature Coefficient=100ppm, Tolerance=1%
R8 R10_1 R10_2 R11_1 R11_2 R17 R18 R19 R20 R28 R29 R30 R31 R32 R33 R35: library part R0003-A.24, "RES CHIP 0402 10k 1% 1/16W", Case Code (Imperial)=0402, Manufacturer=Vishay, Power=62.5mW, Temperature Coefficient=100ppm, Tolerance=1%
R12_1 R12_2: library part R0347-A.1, "RES CHIP 0402 2.4M 1% 1/16W", Case Code (Imperial)=0402, Manufacturer=YAGEO, Power=62.5mW, Temperature Coefficient=100ppm, Tolerance=1%
R13_1 R13_2: library part R0102-A.10, "RES CHIP 0603 470k 1% 1/10W", Case Code (Imperial)=0603, Manufacturer=Yageo, Power=100mW, Temperature Coefficient=100ppm, Tolerance=1%
R23 R24 R25: library part R0224-A.11, "RES CHIP 0402 1k5 1% 1/16W", Case Code (Imperial)=0402, Manufacturer=Vishay, Power=62.5mW, Temperature Coefficient=200ppm, Tolerance=1%
R27 R41: library part R0349-A.1, "RES CHIP 1206 100k 1% 1/4W", Case Code (Imperial)=1206, Manufacturer=YAGEO, Power=250mW, Temperature Coefficient=200ppm, Tolerance=1%
R34: library part R0196-A.14, "RES CHIP 0805 120R 1% 1/8W", Case Code (Imperial)=0805, Manufacturer="Stackpole Electronics", Power=125mW, Temperature Coefficient=100ppm, Tolerance=1%
R36_1 R36_2: library part R0041-A.24, "RES CHIP 0402 910k 1% 1/16W", Case Code (Imperial)=0402, Manufacturer=Vishay, Power=62.5mW, Temperature Coefficient=100ppm, Tolerance=1%
R38_1 R38_2: library part R0113-A.22, "RES CHIP 0603 2k2 1% 1/10W", Case Code (Imperial)=0603, Manufacturer=Vishay, Power=100mW, Temperature Coefficient=100ppm, Tolerance=1%
R40_1 R40_2: library part R0335-A.1, "RES CHIP 0402 150k 5% 1/16W", Case Code (Imperial)=0402, Manufacturer=YAGEO, Power=62.5mW, Temperature Coefficient=100ppm, Tolerance=5%
U1: library part U0276-A.5, "IC TRANSLATOR LEVEL SHIFTER BIDIR 8BIT 20SON", Manufacturer="Texas Instruments"
U2: library part U0362-A.7, "IC 10BASE T1S MAC PHY Ethernet 10Mb Controller, SPI, internal LDO, VQFN 5x5mm", Manufacturer=Microchip
U3_1 U3_2: library part U0397-A.7, "IC Power switch high side, 4.5V to 60V, 3A current limiter, reverse current blocking, short circuit and over current protection, UVLO/OVLO, TQFN-EP 4x4mm", Manufacturer="Analog Devices"
U4: library part U0411-A.1, "IC LINEAR REGULATOR Vout 5V fixed Vin max 45V Iout max 80mA SOT223-3", Manufacturer=Microchip
U5: library part U0317-A.2, "IC RS485/RS422 HALF DUPLEX 20Mbps, 80 nodes, failsafe +-60V, hot swap, ESD 15kV, -40 to 85 °C, PDSO8", Manufacturer=MaxLinear
Y1: library part X0027-A.4, "CRYSTAL 25MHz, frequency tolerance +-30ppm, temperature tolerance +-50ppm, load capacitance 12pF, aging +-2ppm 3.2x2.5mm", Frequency=25MHz, Load Capacitance=12pF, Manufacturer=GEYER, Manufacturer 2=Kyocera, Manufacturer Part Number 2=CX3225SB25000H0FLJCC

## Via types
v1: diameter 0.6, hole 0.3, TOP to BOTTOM, tented both sides, 160 vias

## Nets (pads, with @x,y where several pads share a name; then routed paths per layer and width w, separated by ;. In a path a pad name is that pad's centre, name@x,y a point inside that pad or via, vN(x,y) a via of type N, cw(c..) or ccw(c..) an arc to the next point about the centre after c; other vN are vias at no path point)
+3V3: C2.2 C10.2 C11.2 C12.2 C13.2 C26.2 C27.2 JANALOG.4 L1.1 R1.1 R22.1 T1S_POWER.X U1.5 U2.4 U2.7 U2.17 | length 70.6
  TOP w0.15: C2.2@30.665,39.305 31.315,40.04 33.219,40.04 33.49,39.769 U1.5@33.49,39.238
  TOP w0.3: R22.1@29.665,39.345 29.665,40.75 R1.1@29.69,40.775 ; C26.2@30.165,34.46 C11.2@31.165,34.46 ; C2.2@30.665,39.305 29.665,39.305 29.1,39.305 28.87,39.075 28.87,37.846 29.046,37.67 31.585,37.67 32.96,36.295 32.96,34.776 32.644,34.46 C12.2@32.165,34.46 ; U2.17@31.16,32.295 31.181,32.315 v1(31.181,32.91) 31.173,32.918 31.173,34.452 C11.2@31.165,34.46 ; C12.2@32.102,34.537 32.025,34.46 C11.2@31.165,34.46 ; U2.4@36.14,30.295 36.889,30.295 36.94,30.346 36.94,30.795 ; U2.7@36.14,31.795 36.94,31.795 ; C10.2@37.64,30.795 36.94,30.795 ; C27.2@37.64,31.795 36.94,31.795 ; C13.2@37.64,32.795 37.116,32.795 36.94,32.619 36.94,31.795 ; 36.94,30.795 36.94,31.795
  TOP w0.4: v1(25.409,30.653) 25.447,30.614 26.04,30.614 L1.1@26.185,30.47
  BOTTOM w1.2: v1(25.409,30.653) 26.468,31.712 30.043,31.712 T1S_POWER.X@30.16,31.595 31.26,32.695 35.356,32.695 39.037,29.014 v1(39.037,28.394) v1(39.037,27.394) 39.037,25.419 37.953,24.335 37.953,13.616 35.56,11.223 JANALOG.4@35.56,2.54
+5V: F2.1 JANALOG.5 | length 0.2
  TOP w0.5: F2.1@14.2,38.365 F2.1@14.33,38.235
  other v1: 41.66,30.595 42.46,30.595 41.66,31.595 42.46,31.595 13.4,39.365 14.2,39.365 15,39.365 39.96,42.895 40.96,42.895 39.96,43.895 40.96,43.895
A0_1: JANALOG.9 R19.2 R20.2 | length 21.2
  TOP w0.15: v1@65.333,5.556 v1@65.335,5.554 ; v1@65.335,5.354 R20.2@66.282,5.354 ; R20.2@66.282,5.554 R19.2@66.282,6.554
  BOTTOM w0.15: JANALOG.9@50.8,2.54 52.627,0.713 61.657,0.713 62.257,1.313 62.257,4.813 62.802,5.359 v1@65.33,5.359
  other v1: 65.333,5.356
A1_1: JANALOG.10 R28.2 R29.2 | length 28
  TOP w0.15: R29.2@67.229,11.515 67.232,11.513 R28.2@67.232,10.513 ; R29.2@67.232,11.713 67.238,11.719 67.238,12.636 v1(67.244,12.642)
  BOTTOM w0.15: JANALOG.10@53.34,2.54 53.34,1.331 53.658,1.013 59.057,1.013 59.757,1.713 59.757,3.413 60.257,3.913 60.957,3.913 62.941,5.897 67.601,5.897 67.957,6.253 67.957,12.307 67.644,12.62 67.266,12.62 v1(67.244,12.642)
A2_1: JANALOG.11 R17.1 R24.2 | length 19.9
  TOP w0.15: R24.2@48.755,5.975 48.08,5.3 47.888,5.3 47.8,5.212 47.8,4.68 R17.1@47.805,4.675 45.575,4.675 44.345,3.445 44.345,1.655 44.835,1.165 54.505,1.165 JANALOG.11@55.88,2.54
A3_1: JANALOG.12 R18.1 R25.2 | length 29
  TOP w0.15: R25.2@48.755,8.175 R18.1@48.755,7.075 48.147,6.467 46.545,6.467 44.178,4.1 42.3,4.1 41.9,3.7 41.9,1.5 42.512,0.888 56.768,0.888 JANALOG.12@58.42,2.54
C\S\_\N\_2: U1.4 U2.11 | length 6.8
  TOP w0.15: U1.4@33.09,39.238 33.09,38.422 34.44,37.072 U2.11@34.44,32.995
DIGITAL7_1: JDIGITAL.8 R33.1 R\E\.X U5.2 | length 34.3
  TOP w0.15: v1(21.8,41.2) 21.8,41.195 23.49,39.505 R33.1@25.861,39.505 ; v1(36.57,42.735) 37.19,43.355 37.19,44.162 40.899,47.871 42.791,47.871 JDIGITAL.8@45.72,50.8
  BOTTOM w0.15: v1(21.8,41.2) 25.1,41.2 25.395,41.495 27.06,41.495 R\E\.X@28.16,42.595 29.765,44.2 34.805,44.2 36.199,42.806 36.499,42.806 v1(36.57,42.735)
